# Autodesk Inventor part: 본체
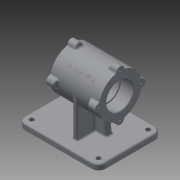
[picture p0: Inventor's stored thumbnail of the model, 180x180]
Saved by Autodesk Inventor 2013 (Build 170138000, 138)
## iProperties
Created: 2015-12
Part Number: 본체
Material: 일반
Document SubType Name: Modeling
Designer: a
Density: 1 g/cm^3
Author: a
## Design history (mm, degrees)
sketch "스케치1"
  geometry: L1 (-58.819, 55)-(60, 55); L2 (60, 55)-(60, -55); L3 (60, -55)-(-58.819, -55); L4 (-58.819, -55)-(-80, -55); L5 (-80, -55)-(-80, 55); L6 (-80, 55)-(-58.819, 55); 2 further points
  constraints: 12 end point, 3 parallel, 1 collinear, 1 horizontal, 1 horizontal alignment, 1 midpoint, 1 perpendicular
  dimensions: "d1" = 80 distance from line of L5 point (0, 0); "d2" = 140 distance between parallel lines of L2 L5; "d3" = 55 distance from line of L1 point (0, 0)
extrude "돌출1" new body sketch "스케치1" distance "d4" = 10; taper "d5" = 0 deg
sketch "스케치2"
  geometry: L1 (55, 10)-(55, 0) reference; L2 (55, 0)-(-55, 0) reference; L3 (-55, 0)-(-55, 10) reference; L4 (-55, 10)-(55, 10) reference; C1 r 37 at (0, 80); 2 further points
  constraints: 1 centre point, 1 midpoint, 1 vertical alignment
  dimensions: "d6" = 74 diameter of C1; "d8" = 80 distance from line of L2 C1.centre
extrude "돌출2" join sketch "스케치2" stored distance "d9" = 85; taper "d10" = 0 deg
sketch "스케치3"
  geometry: L1 (-4, 37)-(4, 37); L2 (4, 37)-(4, -37); L3 (4, -37)-(-4, -37); L4 (-4, -37)-(-4, 37); 3 further points
  constraints: 8 end point, 2 midpoint, 2 parallel, 1 horizontal, 1 horizontal alignment, 1 perpendicular, 1 vertical alignment
  dimensions: "d11" = 8 distance between parallel lines of L4 L2; "d13" = 37 vertical distance of L1.end point (0, 0)
extrude "돌출3" join sketch "스케치3" distance "d14" = 70; taper "d15" = 0 deg
sketch "스케치4"
  geometry: L1 (80, 10)-(80, 0) reference; L2 (80, 0)-(-60, 0) reference; L3 (-60, 0)-(-60, 10) reference; L4 (-60, 10)-(-4, 10) reference; L5 (-4, 10)-(-4, 43) reference; L6 (-4, 43)-(-42.5, 43) reference; L7 (-42.5, 43)-(-42.5, 117) reference; L8 (-42.5, 117)-(42.5, 117) reference; L9 (42.5, 117)-(42.5, 43) reference; L10 (42.5, 43)-(4, 43) reference; L11 (4, 43)-(4, 10) reference; L12 (4, 10)-(80, 10) reference; L13 (15.177, 80)-(25, 0); L14 (25, 0)-(0, 0); L15 (0, 0)-(0, 80); L16 (0, 80)-(15.177, 80); L17 (-42.5, 80)-(60.687, 80)
  constraints: 10 end point, 3 collinear, 1 midpoint, 1 parallel, 1 perpendicular
  dimensions: "d16" = 25 distance of L13.end L14.end; "d17" = 97 deg angle of L13 L14
extrude "돌출4" join sketch "스케치4" stored distance "d18" = 12; taper "d19" = 0 deg
hole "구멍1" diameter "d22" = 42; stored, may be unused: countersink angle "d26" = 90 deg, drill point angle "d28" = 118 deg; dims "d20" = 10, "d21" = 10, "d23" = 6, "d24" = 47, "d25" = 22, "d27" = 8
sketch "스케치5"
  geometry: C1 r 21 at (0, 0) reference; C2 r 37 at (0, 0) reference; C3 r 23.5 at (0, 0); 1 further point
  constraints: 1 centre point, 1 coincident
  dimensions: "d29" = 47 diameter of C3
extrude "돌출5" cut sketch "스케치5" distance "d31" = 22; taper "d32" = 0 deg
fillet "모깎기1" dims "d40" = 12
hole "구멍2" diameter "d43" = 8; stored, may be unused: countersink angle "d47" = 90 deg, drill point angle "d49" = 0 deg; dims "d44" = 6, "d45" = 47, "d46" = 22, "d48" = 10, "d95" = 10, "d96" = 10
fillet "모깎기2" dims "d56" = 3
fillet "모깎기3" dims "d57" = 3
fillet "모깎기4" dims "d58" = 3
fillet "모깎기5" dims "d59" = 3
node "작업 평면2"
  node "작업 평면1"
sketch "스케치7"
  geometry: L1 (-42.5, 37)-(42.5, 37) reference; L2 (-42.5, 37)-(-42.5, -37) reference; 3 further points
  constraints: 1 horizontal alignment, 1 midpoint, 1 other
  dimensions: "d62" = 42.5 distance from line of L2 point (0, 0)
feature "엠보싱1" sketch "스케치7" dims "d1" = 80, "d2" = 140, "d3" = 55, "d11" = 8, "d13" = 37, "d63" = 0.5, "d64" = 0
sketch "스케치9"
  geometry: C1 r 23.5 at (0, 0) reference; C2 r 7 at (-37, 0); 2 further points
  constraints: 2 horizontal alignment, 1 centre point, 1 other
  dimensions: "d67" = 7 radius of C2
extrude "돌출7" join sketch "스케치9" distance "d69" = 15; taper "d70" = 0 deg
hole "구멍3" diameter "d73" = 3.242; stored, may be unused: countersink angle "d77" = 90 deg, drill point angle "d79" = 118 deg; dims "d71" = 10, "d72" = 10, "d74" = 9, "d75" = 47, "d76" = 22, "d78" = 11
chamfer "모따기1" distance "d85" = 1; stored, may be unused: second distance "d86" = 2, angle "d87" = 45 deg
fillet "모깎기6" dims "d88" = 0.3
sketch "스케치11"
  geometry: L1 (-30.526, 117)-(-31.5, 118.621) reference; L2 (-31.5, 118.621)-(-42.5, 118.621) reference; L3 (-42.5, 118.621)-(-42.5, 124) reference; L4 (-42.5, 124)-(-27.5, 124) reference; L5 (-27.5, 124)-(-27.5, 117) reference; L6 (-27.5, 117)-(27.5, 117) reference; L7 (27.5, 117)-(27.5, 124) reference; L8 (27.5, 124)-(42.5, 124) reference; L9 (42.5, 124)-(42.5, 118.621) reference; L10 (42.5, 118.621)-(31.5, 118.621) reference; L11 (31.5, 118.621)-(30.526, 117) reference; L12 (30.526, 117)-(31.5, 115.379) reference; L13 (31.5, 115.379)-(42.5, 115.379) reference; L14 (42.5, 115.379)-(42.5, 104.5) reference; L15 (42.5, 104.5)-(41.5, 103.5) reference; L16 (41.5, 103.5)-(20.8, 103.5) reference; L17 (20.5, 103.2)-(20.5, 101) reference; L18 (20.5, 101)-(-20.5, 101) reference; L19 (-20.5, 101)-(-20.5, 103.2) reference; L20 (-20.8, 103.5)-(-41.5, 103.5) reference; L21 (-41.5, 103.5)-(-42.5, 104.5) reference; L22 (-42.5, 104.5)-(-42.5, 115.379) reference; L23 (-42.5, 115.379)-(-31.5, 115.379) reference; L24 (-31.5, 115.379)-(-30.526, 117) reference; L25 (26.426, 10)-(77, 10) reference; L26 (80, 7)-(80, 0) reference; L27 (80, 0)-(-60, 0) reference; L28 (-60, 0)-(-60, 7) reference; L29 (-57, 10)-(-26.426, 10) reference; L30 (-23.449, 12.634)-(-20.134, 39.634) reference; L31 (-23.111, 43)-(-27.5, 43) reference; L32 (-27.5, 43)-(-27.5, 36) reference; L33 (-27.5, 36)-(-42.5, 36) reference; L34 (-42.5, 36)-(-42.5, 41.379) reference; L35 (-42.5, 41.379)-(-31.5, 41.379) reference; L36 (-31.5, 41.379)-(-30.526, 43) reference; L37 (-30.526, 43)-(-31.5, 44.621) reference; L38 (-31.5, 44.621)-(-42.5, 44.621) reference; L39 (-42.5, 44.621)-(-42.5, 55.5) reference; L40 (-42.5, 55.5)-(-41.5, 56.5) reference; L41 (-41.5, 56.5)-(-20.8, 56.5) reference; L42 (-20.5, 56.8)-(-20.5, 59) reference; L43 (-20.5, 59)-(20.5, 59) reference; L44 (20.5, 59)-(20.5, 56.8) reference; L45 (20.8, 56.5)-(41.5, 56.5) reference; L46 (41.5, 56.5)-(42.5, 55.5) reference; L47 (42.5, 55.5)-(42.5, 44.621) reference; L48 (42.5, 44.621)-(31.5, 44.621) reference; L49 (31.5, 44.621)-(30.526, 43) reference; L50 (30.526, 43)-(31.5, 41.379) reference; L51 (31.5, 41.379)-(42.5, 41.379) reference; L52 (42.5, 41.379)-(42.5, 36) reference; L53 (42.5, 36)-(27.5, 36) reference; L54 (27.5, 36)-(27.5, 43) reference; L55 (27.5, 43)-(23.111, 43) reference; L56 (20.134, 39.634)-(23.449, 12.634) reference; L57 (27.5, 117)-(30.048, 124); L58 (37.937, 117)-(27.5, 117); L59 (30.048, 124)-(26.426, 124); L60 (27.5, 117)-(26.426, 117); L61 (0, 80)-(47.406, 80); L62 (26.426, 117)-(26.426, 124); A1 r 0.3 centre (20.8, 103.2) between (20.8, 103.5) and (20.5, 103.2) reference; A2 r 0.3 centre (-20.8, 103.2) between (-20.5, 103.2) and (-20.8, 103.5) reference; A3 r 3 centre (26.426, 13) between (23.449, 12.634) and (26.426, 10) reference; A4 r 3 centre (77, 7) between (80, 7) and (77, 10) reference; A5 r 3 centre (-57, 7) between (-57, 10) and (-60, 7) reference; A6 r 3 centre (-26.426, 13) between (-26.426, 10) and (-23.449, 12.634) reference; A7 r 0.3 centre (-20.8, 56.8) between (-20.8, 56.5) and (-20.5, 56.8) reference; A8 r 0.3 centre (20.8, 56.8) between (20.5, 56.8) and (20.8, 56.5) reference; 1 further point
  constraints: 12 end point, 3 collinear, 1 perpendicular, 1 point on line, 1 vertical alignment, 2 other
  dimensions: "d89" = 110 deg angle of L57 L58; "d90" = 15 distance from line of L57.start L9; "d91" = 80 distance between parallel lines of L27 L61
  node "절단 모서리 투영5"
revolve "회전1" stored, may be unused: angle "d92" = 90 deg
fillet "모깎기7" dims "d93" = 3
fillet "모깎기8" dims "d94" = 3
node "솔리드1"
mirror "대칭1"
pattern_linear "직사각형 패턴1" dims "d52" = 116, "d55" = 86
pattern_circular "원형 패턴2" dims angle "d83" = 360 deg
mirror "대칭2"
mirror "대칭3"
node "작업축1"
node "절단 모서리 투영1"
node "절단 모서리 투영2"
other parameters: "d60" = -45 deg, "d61" = -37.5
